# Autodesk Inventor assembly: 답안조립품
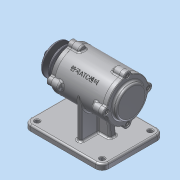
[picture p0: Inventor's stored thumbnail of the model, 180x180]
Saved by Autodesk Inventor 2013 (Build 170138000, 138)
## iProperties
Created: 2015-12
Part Number: 답안조립품
Document SubType Name: Assembly
Designer: dgall
Author: dgall
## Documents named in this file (11)
- C:\Users\dgall\Desktop\451207V1033\답안조립품.iam
- C:\Users\dgall\Desktop\451207V1033\1-본체.ipt
- C:\Users\dgall\Desktop\451207V1033\V-벨트풀리.ipt
- C:\Users\dgall\Desktop\451207V1033\너트 M12x1.25.ipt
- C:\Users\dgall\Desktop\451207V1033\베어링 6204.ipt
- C:\Users\dgall\Desktop\451207V1033\오일실.ipt
- C:\Users\dgall\Desktop\451207V1033\볼트 M4 x 12.ipt
- C:\Users\dgall\Desktop\451207V1033\축.ipt
- C:\Users\dgall\Desktop\451207V1033\커버.ipt
- C:\Users\dgall\Desktop\451207V1033\커버2.ipt
- C:\Users\dgall\Desktop\451207V1033\키(4 x 4 x 12).ipt
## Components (7 placed, 6 different names)
1. 1-본체:1
2. V-벨트풀리:1
3. KS B 1012 클래스 1 일반 - 미터 M12x1.25:1
4. KS B 2023 6204 - 20 x 47 x 14:1
5. KS B 2023 6204 - 20 x 47 x 14:2
6. KS B 2804 D D - 20 32 8:1
7. KS B 1311 (I) 4 x 4 x 12:1 — 각도:1
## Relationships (1: Angle 1)
- 각도:1 [Angle]: KS B 1311 (I) 4 x 4 x 12:1
